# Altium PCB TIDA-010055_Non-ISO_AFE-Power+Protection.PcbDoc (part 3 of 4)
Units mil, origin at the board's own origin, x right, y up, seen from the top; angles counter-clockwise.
Board outline 3622.05 x 4330.71 mil, 4 copper layers (Top Layer, GND Layer, PWR Layer, Bottom Layer), stack 63.6 mil thick; 398 components, 177 nets, 1104 pads, 428 vias.
Unrouted connection lines stored in the file: 1.
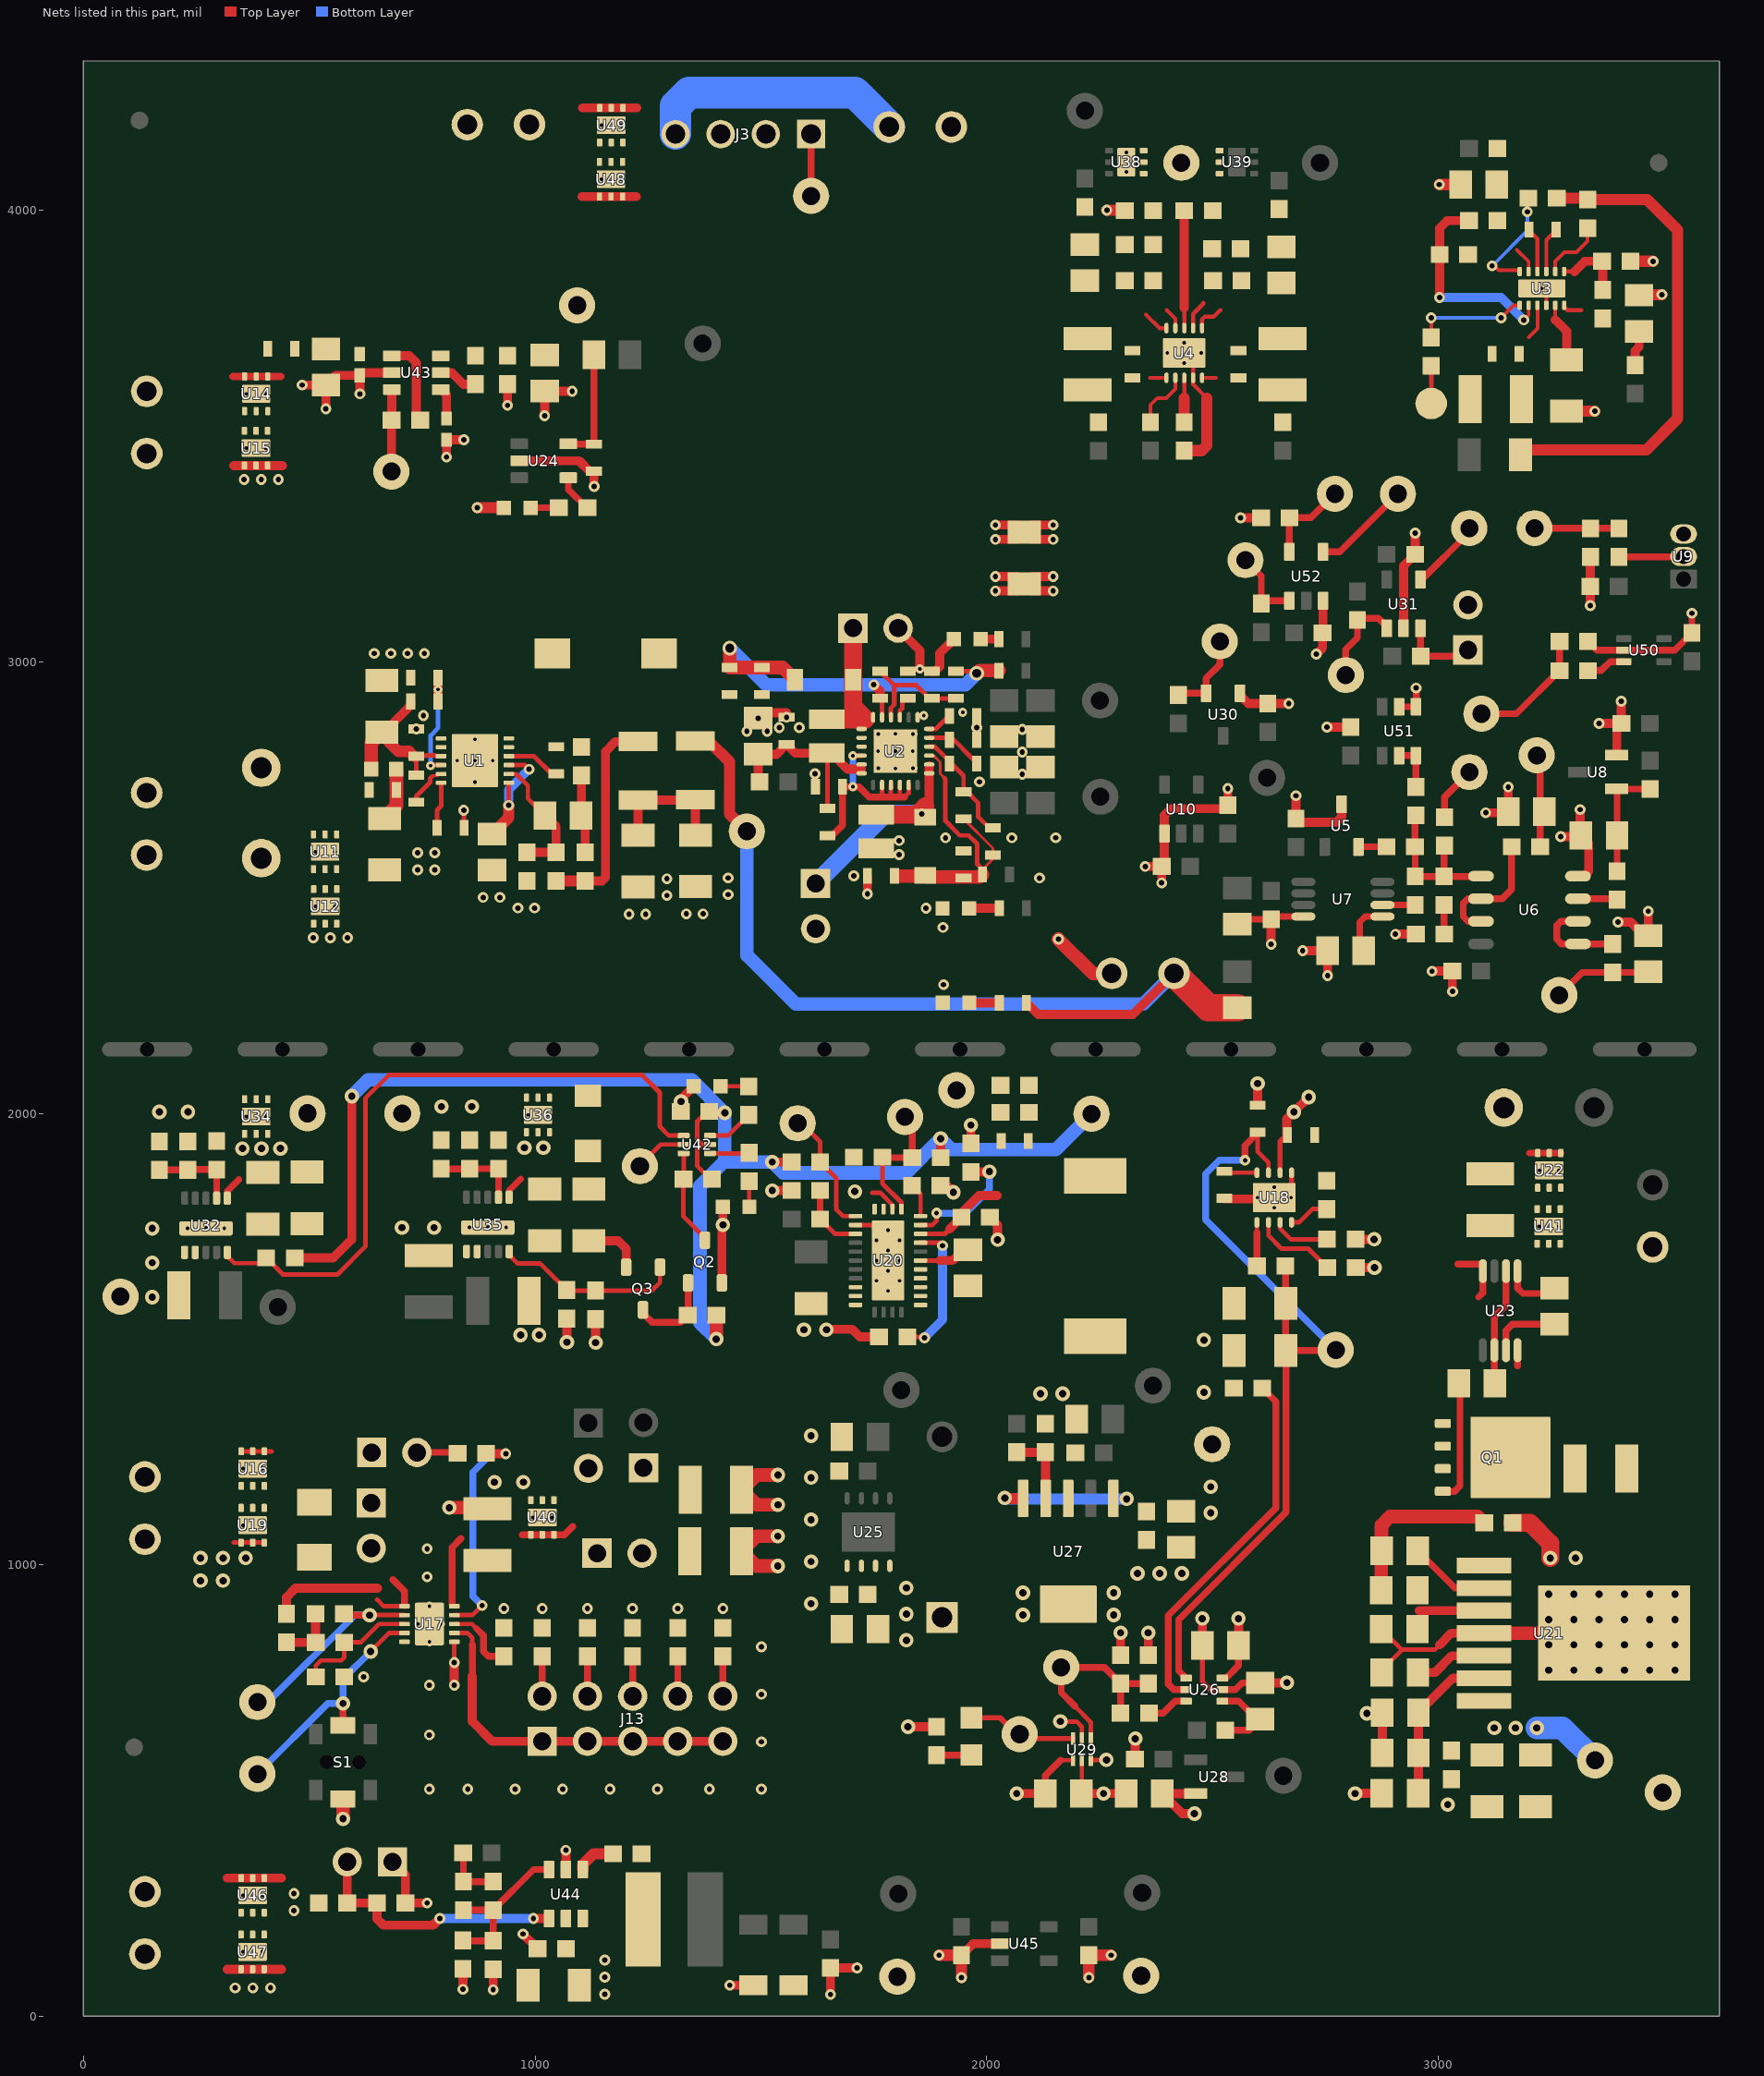
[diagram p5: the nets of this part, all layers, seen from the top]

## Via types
v1: diameter 24, hole 12, Top Layer to Bottom Layer, tented both sides, 201 vias
v2: diameter 32, hole 16, Top Layer to Bottom Layer, tented both sides, 134 vias
v3: diameter 19.68, hole 7.87, Top Layer to Bottom Layer, 78 vias
v4: diameter 20, hole 8, Top Layer to Bottom Layer, tented both sides, 11 vias
v5: diameter 32, hole 20, Top Layer to Bottom Layer, tented both sides, 2 vias
v6: diameter 24, hole 10, Top Layer to Bottom Layer, tented both sides, 2 vias

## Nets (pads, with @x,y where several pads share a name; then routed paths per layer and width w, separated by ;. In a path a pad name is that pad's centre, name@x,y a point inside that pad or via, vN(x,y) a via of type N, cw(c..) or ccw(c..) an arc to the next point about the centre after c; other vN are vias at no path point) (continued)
AGND: C9.1 C32.1 C33.2 C34.2 C35.2 C37.2 C39.2 C41.2 C42.2 C43.1 C44.2 C45.2 C46.2 C47.1 C48.2 C49.1 C50.2 C51.2 C52.2 C53.2 C54.2 C55.2 C56.1 C57.1 C58.2 C59.2 C99.2 C100.2 C135.1 C136.1 C137.2 C138.1 C139.2 J3.3 J15.2 J20.1 J21.1 R32.1 R35.1 R37.1 R51.1 TP32.1 U3.4 U3.13@3229.36,3826.82 U4.4 U4.11 U5.3 U6.4 U7.4 U8.2 U9.3 U10.1 U30.1 U31.2 U38.1 U38.2 U38.3 U38.7@2309,4106.65 U39.4 U39.5 U39.6 U49.4 U49.5 U49.6 U50.2 U51.1 U51.2 U52.3 | length 3644.7
  Top Layer w8: v3(3229.36,3826.82) U3.13@3239.2,3816.98
  Top Layer w9: U4.11@2437.4,3684 2457.09,3664.32 U4.4@2457.09,3628.88 2457.09,3614.32 2487.4,3584 ; U3.4@3239.2,3789.42 U3.13@3239.2,3816.98
  Top Layer w15: C53.2@2554.81,2419.23 2565.31,2429.74 C54.2@2629.81,2429.74 ; C54.2@2635.92,2435.85 U7.4@2701.21,2435.85 ; U51.2@2913,2900.44 U51.1@2950.4,2900.44 2951,2901.04 v1(2951,2942) ; C136.1@3331.25,3045.39 3350.64,3026 U50.2@3410.93,3026 3523.54,3026 C135.1@3561.61,3064.08 v1(3561.61,3107.61)
  Top Layer w20: 1104.61,4226.71 U49.6@1142.98,4226.71 U49.5@1168.57,4226.71 U49.4@1194.16,4226.71 1224.84,4226.71 ; v1(2019.16,3271.1) 2067.24,3271.1 R51.1@2083.16,3287.01 ; v1(2019.16,3302.92) 2067.24,3302.92 R51.1@2083.16,3287.01 ; v1(2147.16,3271.1) 2099.07,3271.1 R51.1@2083.16,3287.01 ; v1(2147.16,3302.92) 2099.07,3302.92 R51.1@2083.16,3287.01 ; v1(2351,2546.72) C58.2@2387.38,2546.7 ; v1(2387.38,2510.35) C58.2@2387.38,2546.7 ; C58.2@2393.47,2552.8 U10.1@2393.47,2619.57 2393.47,2660.2 2408,2674.72 2525.9,2674.72 C59.2@2533.87,2682.7 v1(2533.9,2719.08) ; U30.1@2560.65,2926.31 2579.46,2907.5 C99.2@2622.25,2907.5 v1(2669.04,2907.5) ; v1(2562,3319) C138.1@2607.5,3319 ; v1(2629.81,2374.42) C54.2@2629.81,2429.74 ; v1(2684.81,2703.53) C46.2@2684.81,2652.73 2692.81,2644.72 2774,2644.72 2785.81,2656.53 U5.3@2785.81,2684.48 ; v1(2699.49,2360.23) C48.2@2754.81,2360.23 v1(2754.81,2304.92) ; v1(2729.85,3017) 2743.56,3030.71 C139.2@2743.56,3064.02 2744.76,3065.22 U52.3@2744.76,3135.32 ; v1(2753.5,2855.5) C137.2@2806,2855.5 ; v1@2905.51,2397.23 C55.2@2950.31,2397.23 ; U31.2@2923,3078 2923.06,3078.07 2923.06,3212.77 C100.2@2948.5,3238.2 v1(2948.5,3285.13) ; v1@2986.51,2315.23 C47.1@3031.31,2315.23 v1@3031.31,2270.43 ; v1(3105,2665.72) 3152.3,2665.72 C52.2@3154.81,2668.23 3155,2668.43 v1(3155,2722.72) ; v1(3271,2612.72) 3313.3,2612.72 C51.2@3315.3,2614.73 ; U6.4@3309.09,2525.23 3322.51,2525.23 3333,2535.72 3333,2598.04 C51.2@3315.81,2615.23 3314,2617.04 v1(3314,2672.72) ; v1(3336.5,3124.5) C56.1@3336.5,3167 3336.5,3232.01 C57.1@3337,3232.5 ; v1(3355.69,2863.72) C49.1@3404.35,2863.72 ; U8.2@3395.19,2793.13 3395.19,2853.56 C49.1@3405.35,2863.72 ; v1(3398,2423.72) 3426,2423.72 3456,2393.72 C50.2@3464.85,2393.72 v1(3464.85,2447.57) ; C49.1@3404.85,2864.23 v1(3404.85,2912.88)
  Top Layer w25: v1(2266,4000) 2304.91,4000 R35.1@2305.91,3999 ; C42.2@2437.4,3467.5 2475.91,3467.5 2487.4,3479 2487.4,3584 ; v1(3002.19,4056.98) C34.2@3049.2,4056.98 ; C45.2@3284.2,3554.9 v1(3346.36,3554.9) ; R37.1@3425.7,3886.98 v1(3475.7,3886.98) ; C39.2@3444.2,3811.98 3445.44,3813.23 v1(3494.83,3813.23)
  other v1: 3031.82,2269.92 2986,2314.72 2905,2396.72
  other v3: 2437.4,3661.36 2400,3684 2474.8,3684 2437.4,3706.64 2309,4085 2309,4128.31
DCDC_+10P5V: C102.1 C103.1 R88.2 TP20.1 U32.6 U34.4 U34.5 U34.6 | length 51.5
  Top Layer w15: U32.6@318.35,1812.08 318.35,1827.35 344,1853
  other v2: 352,1922 394,1922 436,1922
DCDC_-10P5V: C105.2 C106.2 C107.2 D4.2 Q3.2 R92.1 R93.1 TP22.1 U35.1 U35.2 U35.11@895.2,1747.09 U36.1 U36.2 U36.3 U36.7@1006.37,1996.6 | length 130.6
  Top Layer w20: C107.2@1119.09,1717.78 1183.7,1717.78 1201.6,1699.88 Q3.2@1201.6,1659.24
  other v2: 705.09,1746.86 776.09,1746.94 792.75,2014.94 859.75,2014.94
  other v3: 854.65,1747.09 895.2,1747.09 935.75,1747.09 984.72,1996.6 1028.03,1996.6
EXT_5V: C61.1 C84.1 C121.1 R104.2 R113.1 TP43.1 U24.5 U43.6 | length 255.2
  Top Layer w15: U24.5@1073.32,3482.6 1073.72,3482.2 C84.1@1130.18,3482.2 1130.18,3680.05 R113.1@1129.99,3680.25
GND: C3.2 C4.2 C5.2 C8.2 C10.2 C16.2 C17.2 C18.2 C19.2 C21.2 C22.2 C23.2 C25.1 C26.1 C27.1 C28.1 C29.2 C30.2 C31.2 C60.2 C61.2 C84.2 C120.2 C121.2 C122.2 D1.2 D6.2 D10.1 D11.2 J1.2 J4.2 J6.1 J8.2 J12.2 L5.2 R8.1 R9.1 R10.1 R11.1 R16.1 R51.2 U1.1 U1.2 U1.13 U2.2 U2.3 U2.19 U2.25 U12.4 U12.5 U12.6 U15.4 U15.5 U15.6 U24.2 U43.2 | length 1700.5
  Top Layer w10: v1(841.88,2671.43) 841.88,2633.01 C10.2@842.73,2632.16
  Top Layer w20: 332.76,3434.69 U15.4@356.4,3434.69 U15.5@381.99,3434.69 U15.6@407.58,3434.69 440.76,3434.69 ; v1(484.08,3612.97) C60.2@536.66,3612.97 ; v1(536.66,3560.4) C60.2@536.66,3612.97 ; v1(611.81,3593.25) C120.2@611.81,3634.63 ; U43.2@682.67,3640.25 617.43,3640.25 C120.2@611.81,3634.63 ; v1(803.81,3453.25) C122.2@803.81,3491.63 v1(842.19,3491.63) ; v1(938.99,3568.01) C61.2@938.99,3614.75 ; U24.2@965.05,3445.2 1097.5,3445.2 1120.5,3422.2 C84.2@1130.18,3422.2 v1@1130.18,3388.61 ; v1(1020.99,3545) C121.2@1020.99,3599.25 v1(1082.25,3599.25) ; v1(1493.73,2875.16) 1505.73,2887.16 v1@1556.73,2887.16 ; C28.1@1735.73,2526.16 1736,2525.89 v1(1736,2486) ; J8.2@1804.73,3072.16 1851.73,3025.16 v4(1851.73,2984.16) ; R16.1@1878.73,2979.16 1885.41,2979.16 1895.88,2989.63 1895.88,3018.83 D6.2@1927.2,3050.16 ; D10.1@1902.2,2454.16 D10.1@1902.32,2454.04 ; v1(2019.16,3156.92) 2067.24,3156.92 R51.2@2083.16,3172.84 ; v1(2019.16,3188.75) 2067.24,3188.75 R51.2@2083.16,3172.84 ; v1(2147.16,3156.92) 2099.07,3156.92 R51.2@2083.16,3172.84 ; v1(2147.16,3188.75) 2099.07,3188.75 R51.2@2083.16,3172.84 ; C60.2@536.66,3612.97 558.31,3634.63 C120.2@611.81,3634.63
  Top Layer w25: v1(872.02,3341.2) D11.2@931.07,3341.2
  Top Layer w30: v1(2158.85,2385.72) 2234.85,2309.72 J6.1@2276.85,2309.72
  other v1: 1904.43,2285 508.66,2388.76 546.66,2388.76 584.66,2388.76 1903,2411.68 1207.88,2441.04 1244.88,2441.04 1334.88,2441.76 1371.88,2441.76 961.88,2454.67 998.88,2454.67 1865.53,2454.16 884.88,2478.17 921.88,2478.17 1291.88,2482.43 1427.61,2484.43 1291.88,2519.43 1427.61,2521.43 2116.73,2521.16 1705.73,2526.16 739.88,2539.16 777.88,2539.16 1806,2573 739.88,2577.16 777.88,2577.16 1806,2604 1908.73,2610.16 2055.73,2610.16 2152.88,2610.43 1983.73,2734.16 2078.73,2751.16 1619.73,2752.16 2078.73,2800.16 1468.73,2846.16 1513.73,2846.16 2078.73,2850.16 736.73,2851.16 1540.73,2854.16 1584.73,2854.16 1977.73,2854.16 1556.73,2877.16 752.73,2881.16 643.73,3018.51 680.73,3018.51 717.73,3018.51 754.73,3018.51 1130.6,3388.2 355.48,3403.68 393.48,3403.68 431.48,3403.68
  other v3: 866.73,2733.91 1797.73,2763.77 827.36,2781.16 866.73,2781.16 906.1,2781.16 1759.35,2802.16 1797.73,2802.16 1836.12,2802.16 866.73,2828.4 1797.73,2840.54
  other v4: 1759.73,2764.16 1836.73,2764.16 1759.81,2840.08 1836.73,2840.16 1860.73,2881.16 1946.73,2888.16
GND1: C63.2 C64.2 C65.2 C66.2 C68.2 C69.2 C70.1 C71.2 C72.2 C74.2 C76.2 C77.2 C78.2 C79.2 C80.2 C81.2 C82.2 C83.1 C85.1 C86.1 C87.1 C88.1 C89.1 C90.1 C91.2 C92.1 C93.1 C94.1 C95.1 C96.1 C97.1 C98.2 C101.2 C102.2 C103.2 C104.2 C106.1 C107.1 C119.2 C133.2 C134.2 D4.1 D14.2 D15.2 J11.2 J14.1 Q2.2 R6.2 R57.1 R69.1 R70.1 R72.2 R73.1 R74.1 R81.1 R84.1 R89.1 R90.1 R91.2 R98.1 R110.1 R111.1 S1.1 TP21.1 TP26.1 TP39.1 TP41.1 U17.6 U18.5 U18.9 U19.4 U19.5 U19.6 U20.13 U20.14 U20.15 U20.17 U20.24 U20.25 U20.26 U20.31@1781.43,1673.99 U21.4 U21.8 U25.1 U26.2 U27.3 U27.6 U28.2 U29.1 U29.3 U29.5 U32.1 U32.2 U32.11@271.11,1745.15 U34.1 U34.2 U34.3 U34.7@382.28,1993 U35.6 U36.4 U36.5 U36.6 U40.1 U40.2 U40.3 U40.7@1016,1105 U41.4 U41.5 U41.6 U42.2 | length 3710.1
  Top Layer w10: 332.25,1049.43 U19.4@348.96,1049.43 U19.5@374.55,1049.43 U19.6@400.14,1049.43 ; v1(820.96,783.41) U17.6@820.96,829.59 ; TP21.1@1230,1883 1278,1931 U42.2@1328.87,1931 ; U20.17@1709.58,1752.73 1743.95,1752.73 1781.43,1715.24 v3(1781.43,1696.43) U20.31@1781.43,1673.99 ; 1747,1824 1764.28,1824 1791.28,1797 U20.13@1791.28,1788.16 ; v2(2163,653) 2199,653 2210.68,641.32 U29.5@2210.68,615.26 ; 2163.23,567.23 U29.1@2191,567.23 ; U29.3@2230.37,568.02 v2(2265,568) ; R69.1@2873.86,857.68 2919.65,811.89 ; C77.2@2874.86,767.1 2919.65,811.89 ; 3003.12,822.89 2992.12,811.89 2919.65,811.89
  Top Layer w12: C89.1@2477.68,821.64 2477.68,740.32 2494.36,723.64 U26.2@2522.04,723.64 ; U18.9@2636.73,1813.43 v3(2674.13,1813.43) ; U18.9@2675.12,1813.43 U18.5@2675.12,1868.54
  Top Layer w15: U35.6@942.44,1814.02 942.44,1829.3 968.09,1854.94 ; v2@1413.94,1752 v2@1415.47,1753.53 ; C97.1@2129.68,493.64 2129.68,533.68 2163.23,567.23 ; U26.2@2522.04,723.64 2550.68,723.64 2565.68,738.64 C96.1@2605.68,738.64
  Top Layer w20: v1(820.96,733.41) v1(820.96,783.41) ; v2(1070.28,1493) R98.1@1070.28,1545.23 ; v2(1134,1492) R6.2@1134,1544.23 ; C119.2@1330.38,2001 1323,2008.38 v2(1323,2026) 1323,2031.53 D14.2@1351.47,2060 ; Q2.2@1413.5,1624.34 1413.5,1751.56 v2@1413.94,1752 ; v2@1415.47,1753.53 D15.2@1415.47,1793 ; v2(1525.21,1828.99) R73.1@1567.94,1828.99 ; v2(1645.12,1520.89) 1646.23,1522 1702,1522 1719,1505 C70.1@1761.5,1505 ; C82.2@1897.5,1840 1911,1840 v2(1926,1825) ; v2(1965,1974) 1965,1933.5 R72.2@1965.12,1933.39 ; C83.1@2007.12,1769.89 2024.12,1752.89 v2(2024.12,1719.89) ; v2(2066.36,493.64) C97.1@2129.68,493.64 ; C91.2@2296.68,800.14 v2(2296.68,849.68) ; R81.1@2357.68,800.14 v2(2357.68,849.68) ; C90.1@2388.68,493.64 C90.1@2389.08,493.24 ; v2(2460,449) 2433.32,449 C90.1@2389.08,493.24 ; U28.2@2460.38,493.24 C90.1@2389.08,493.24 ; C89.1@2477.68,821.64 v2@2477.68,879.6 ; C98.2@2525.99,1810.27 2633.57,1810.27 U18.9@2636.73,1813.43 ; C63.2@2600,2019.5 v2(2600,2066) ; C96.1@2605.68,738.64 v2@2663.64,738.64 ; R111.1@2816.5,1721 v2(2858,1721) ; v2@2817.04,494 R70.1@2875,494 ; R110.1@2817.08,1658.39 v2(2858.58,1658.39) ; 3003.12,822.89 3028.9,848.68 U21.4@3101.26,848.68
  Top Layer w30: v2(574.59,437.63) 574.59,438.63 S1.1@574.59,481.26 ; v2(809.84,1126.66) 890.38,1126.66 C66.2@893.84,1123.19 ; v2(1537.46,997.36) 1489.93,997.36 C69.2@1456.93,1030.36 1489.93,1063.36 v2(1537.46,1063.36) ; v2(1537.74,1132.89) 1490.2,1132.89 C68.2@1457.2,1165.89 1490.2,1198.89 v2(1537.74,1198.89) ; U21.4@3101.26,848.68 U21.8@3388.86,848.68
  Top Layer w40: C79.2@3164.5,1093 3203,1093 3248,1048 v2(3248,1015)
  other v2: 3021,469 2815.68,493.64 2665,739 3244.12,766.89 3300.12,766.89 3356.12,766.89 3412.12,766.89 3468.12,766.89 3524.12,766.89 3244.12,822.89 3300.12,822.89 3356.12,822.89 3412.12,822.89 3468.12,822.89 3524.12,822.89 3244.12,878.89 3300.12,878.89 3356.12,878.89 3412.12,878.89 3468.12,878.89 3524.12,878.89 2477.32,880.96 2080.07,889 2281,889 1611,914 3244.12,934.89 3300.12,934.89 3356.12,934.89 3412.12,934.89 3468.12,934.89 3524.12,934.89 2080.07,938 2281,938 259,965 309,965 2334,981 2383,981 2432,981 1611,1007 259,1015 309,1015 359,1015 3304,1015 1611,1100 910,1183 974,1183 1611,1193 1611,1286 2119,1379 2168,1379 967.75,1508.89 1008.71,1508.89 1595.12,1520.89 152,1593 152,1669 152,1745 1416,1753 1708,1827 976.09,1923.94 1018.09,1923.94 168,2003 231.11,2003
  other v3: 994.35,1105 1037.65,1105 1781.43,1606.66 1755.84,1629.1 1807.02,1629.1 1781.43,1651.54 1755.84,1673.99 1807.02,1673.99 1755.84,1718.87 1807.02,1718.87 1781.43,1741.31 230.56,1745.15 271.11,1745.15 311.66,1745.15 2636.73,1790.79 2599.33,1813.43 2636.73,1836.06 360.63,1993 403.94,1993
GND_S: C123.2 C124.2 C125.2 C126.2 C129.2 C130.2 C131.1 C132.2 J18.1 J19.2 R107.1 R109.1 TP35.1 TP37.1 U44.2 U45.2 U47.4 U47.5 U47.6 | length 914.5
  Top Layer w20: 318.14,104.43 U47.4@348.82,104.43 U47.5@374.41,104.43 U47.6@400,104.43 438.37,104.43 ; J18.1@684,342 712.99,313.01 R107.1@712.99,251 v1(761,251) ; v1(840.07,59.98) C132.2@840.07,105.48 ; v1(907.07,58.98) R109.1@907.07,104.48 ; v1(973.07,182.48) C124.2@1005.57,149.98 ; U44.2@1068.07,325.11 v1(1068.07,367.98) ; v1(1431.07,68.98) 1483,68.98 C129.2@1483.07,69.05 ; v1(1654.07,48.55) C131.1@1654.07,107.48 v1(1713,107.48) ; C125.2@1944.07,135.48 1969.5,160.91 2028.94,160.91 U45.2@2028.94,160.98
  Top Layer w25: v1(1894.57,135.48) C125.2@1944.07,135.48 v1(1944.07,85.98) ; v1(2226.07,85.98) C126.2@2226.07,135.48 v1(2275.57,135.48)
  other v1: 336,63 375,63 414,63
NetC1_1: C1.1 C6.1 C7.1 J6.2 L2.2 R1.1 R7.2 R112.1 TP24.1 | length 2577.3
  Top Layer w20: C1.1@1110.88,2514.94 1148.39,2514.94 1155.92,2522.47 1155.92,2801.56 1177.71,2823.35 C6.1@1227.88,2823.35 ; R1.1@2087.85,2244.72 2113.85,2218.72 2323.65,2218.72 J6.2@2414.65,2309.72
  Top Layer w25: R7.2@1046.32,2514.94 C1.1@1110.88,2514.94 ; C7.1@1354.88,2824.35 1384.65,2824.35 1430.42,2778.59 1430.42,2662.9 TP24.1@1468.88,2624.43
  Top Layer w60: J6.2@2414.65,2309.72 2490.37,2234 R112.1@2555,2234
  Bottom Layer w30: TP24.1@1468.88,2624.43 1468.88,2350.12 1577,2242 2346.92,2242 J6.2@2414.65,2309.72
NetC1_2: C1.2 C11.1 R5.2 | length 174.5
  Top Layer w20: R5.2@1102.47,2748.45 1102.47,2660.02 C11.1@1101.88,2659.43 1110.88,2650.43 C1.2@1110.88,2577.93
NetC2_1: C2.1 U1.10 | length 121.2
  Top Layer w10: U1.10@941.54,2791 997.48,2791 1036.54,2751.94 C2.1@1046.54,2751.94
NetC2_2: C2.2 L2.1 R5.1 U1.11 U1.12
NetC3_1: C3.1 L1.1 R2.1 | length 117.2
  Top Layer w30: C3.1@666.73,2653.24 666.73,2655.16 692.73,2681.16 R2.1@692.73,2716.16 L1.1@692.73,2759.72
NetC4_1: C4.1 C5.1 L1.2 R3.1 R4.2 U1.3 | length 402.3
  Top Layer w10: R3.1@736.73,2749.16 736.73,2787.51 741.26,2792.03 758.26,2792.03 759.12,2792.89 778.35,2792.89 780.24,2791 U1.3@791.93,2791
  Top Layer w20: C4.1@637.17,2820.51 C4.1@637.17,2845.87 ; C4.1@660.73,2844.07 665.4,2844.07 724.73,2903.41 R4.2@724.73,2912.16
  Top Layer w25: C4.1@659.73,2838.76 696.73,2801.76 720.81,2801.76 C5.1@731.41,2791.16
  Top Layer w30: L1.2@637.17,2762.16 637.17,2820.51 C4.1@660.73,2844.07
NetC6_2: C6.2 C7.2 R8.2 R9.2 | length 283.6
  Top Layer w20: R9.2@1227.88,2615.48 C6.2@1227.88,2693.43 1353.88,2693.43 C7.2@1354.88,2694.43 R8.2@1354.88,2616.2
NetC8_1: C8.1 U1.7 U1.9 | length 276.3
  Top Layer w10: v1(941.54,2682.13) U1.7@941.54,2731.94 ; U1.9@941.54,2771.31 977.37,2771.31 v1(986.74,2761.94)
  Top Layer w25: C8.1@904.88,2618.43 941.54,2655.09 v1(941.54,2682.13)
  Bottom Layer w20: v1(941.54,2682.13) 941.54,2716.74 v1(986.74,2761.94)
NetC9_2: C9.2 C33.1 R19.1 R31.1 R36.1 U3.3 | length 1173.8
  Top Layer w8: 3200.2,3718.98 3219.52,3738.3 U3.3@3219.52,3789.42
  Top Layer w20: R36.1@3327.19,4026.98 R36.1@3330.7,4023.48
  Top Layer w25: R19.1@3182.36,3458.82 3192.76,3469.23 3460.7,3469.23 3529.98,3538.5 3529.98,3956.08 3462.58,4023.48 R36.1@3330.7,4023.48 ; R31.1@3262.19,4026.98 R36.1@3327.19,4026.98
NetC10_1: C10.1 U1.6 | length 103.6
  Top Layer w10: C10.1@782.73,2632.16 782.73,2671.28 791.93,2680.48 U1.6@791.93,2731.94
NetC11_2: C11.2 R7.1 R11.2 U1.8 | length 291.1
  Top Layer w10: U1.8@941.54,2751.63 957.88,2751.63 983.88,2725.63 983.88,2697.43 C11.2@1021.88,2659.43
  Top Layer w20: R11.2@981.88,2577.93 R7.1@1046.32,2577.93 1046.32,2635 C11.2@1021.88,2659.43
NetC18_1: C18.1 C19.1 C20.1 D7.1 R15.2 R22.1 U2.23 | length 967
  Top Layer w10: U2.23@1768.2,2876.96 C20.1@1768.2,2918.63 ; R15.2@1931.73,2979.16 1973.16,2979.16 v5(1977.88,2974.43)
  Top Layer w20: v1(1750.05,2949.16) 1763.73,2935.48 C20.1@1763.73,2919.16
  Top Layer w30: v5(1430.88,3030.43) 1430.73,3030.28 C18.1@1430.73,2987.43 C19.1@1501.88,2987.43 1547.99,2987.43 D7.1@1575.26,2960.16 ; v5(1977.88,2974.43) 1983.88,2980.43 R22.1@2026.88,2980.43
  Bottom Layer w30: v5(1430.88,3030.43) 1512.16,2949.16 v1(1750.05,2949.16) 1952.61,2949.16 v5(1977.88,2974.43)
NetC20_2: C20.2 R15.1 R16.2 U2.22 | length 310.5
  Top Layer w10: C20.2@1763.73,2979.16 1794.11,2948.78 1794.11,2903.82 ; U2.22@1787.89,2876.96 1787.89,2897.16 ; 1787.89,2897.61 1794.11,2903.82 ; R15.1@1931.73,2919.16 R16.2@1878.73,2919.16 1872.73,2919.16 1843.46,2948.43 1795.36,2948.43 1795.36,2905.08 1794.11,2903.82
NetC21_1: C21.1 R17.2 U2.17 | length 120
  Top Layer w10: U2.17@1872.54,2831.69 1911.2,2831.69 C21.1@1915.73,2827.16 ; C21.1@1919.73,2834.48 R17.2@1972.73,2781.48
NetC22_1: C22.1 C23.1 L3.2 L4.1 R20.2 U2.5 U2.6 | length 443.9
  Top Layer w10: R20.2@1647.73,2675.16 L4.1@1647.73,2795.76
  Top Layer w20: L3.2@1497.24,2734.16 1493.73,2737.66 C22.1@1493.73,2795.16 1534.73,2795.16 C23.1@1556.73,2817.16 1576.13,2797.76 L4.1@1645.73,2797.76 1656.13,2797.76 1691.73,2762.16 1722.73,2762.16
NetC24_1: C24.1 R17.1 R18.2 U2.16 | length 258.9
  Top Layer w10: U2.16@1872.54,2812 1884.82,2812 1897.22,2799.6 1897.22,2799.54 1948.73,2748.03 C24.1@1948.73,2712.16 1956.73,2712.16 1980.73,2688.16 1980.73,2657.16 R18.2@2005.73,2632.16 ; R18.2@2001.73,2632.16 R18.2@2005.73,2632.16 ; R18.2@2013.73,2632.16 R18.2@2005.73,2632.16
NetC24_2: C24.2 C27.2 C28.2 D8.2 R18.1 R23.1 U2.15 | length 672.3
  Top Layer w6: U2.15@1872.54,2792.31 1882,2792.31 1896.73,2777.58 1896.73,2752.16 1905.73,2743.16 ; C24.2@1948.73,2652.16 2013.73,2587.16 R18.1@2013.73,2572.16 2013.73,2563.16 1990.73,2540.16 R23.1@1990.73,2529.16
  Top Layer w10: 1905.73,2743.16 1908.61,2740.28 1908.61,2647.71 1940.88,2615.43 1960.16,2615.43 1979.11,2596.49 1979.11,2551.78 R23.1@1990.73,2540.16
  Top Layer w30: C28.2@1800.73,2525.16 1862.07,2525.16 D8.2@1863.88,2526.96 1867.74,2523.11 1984.68,2523.11 R23.1@1990.73,2529.16
NetC29_1: C29.1 R20.1 U2.4 U2.8 U2.9 U2.10 U2.11 | length 474.8
  Top Layer w10: v4(1703.73,2792.16) 1703.89,2792.31 U2.4@1722.93,2792.31 ; 1768.2,2700.64 U2.8@1768.2,2727.35 ; 1787.89,2700.33 U2.9@1787.89,2727.35 ; 1807.57,2700.33 U2.10@1807.57,2727.35 ; 1818.23,2700.17 1827.26,2709.2 U2.11@1827.26,2727.35
  Top Layer w15: R20.1@1647.73,2615.16 1658.23,2615.16 1680.73,2637.66 C29.1@1680.73,2723.16 v4(1703.73,2723.16) 1717.21,2723.16 1740.19,2700.17 1818.23,2700.17
  Bottom Layer w15: v4(1703.73,2723.16) v4(1703.73,2792.16)
NetC30_1: C30.1 U2.18 | length 55.1
  Top Layer w10: U2.18@1872.54,2851.37 1886.94,2851.37 C30.1@1915.73,2880.16
NetC31_1: C31.1 U2.21 | length 48.1
  Top Layer w10: U2.21@1807.57,2876.96 1807.57,2892.02 1813.23,2897.67 1813.23,2910.66 C31.1@1821.73,2919.16
NetC32_2: C32.2 C35.1 R26.2 U4.1 | length 36.6
  Top Layer w8: 2361.4,3628.88 U4.1@2398.03,3628.88
NetC34_1: C34.1 R24.1 R27.2 U3.11 | length 58.4
  Top Layer w8: 3174.2,3911.98 3199.83,3886.35 U3.11@3199.83,3864.23
NetC36_1: C36.1 C37.1 R25.1 R28.2 U4.10 | length 58
  Top Layer w9: 2352.4,3769 2382.28,3739.12 U4.10@2398.03,3739.12
NetC36_2: C36.2 R28.1 R35.2 U4.9 | length 47.9
  Top Layer w9: 2398.4,3779 2417.72,3759.69 U4.9@2417.72,3739.12
NetC38_1: C38.1 U3.9 | length 102.3
  Top Layer w9: U3.9@3239.2,3864.23 3239.2,3933.99 C38.1@3262.19,3956.98
NetC38_2: C38.2 U3.10 | length 101.2
  Top Layer w9: C38.2@3199.2,3956.98 3219.52,3936.67 U3.10@3219.52,3864.23
NetC39_1: C39.1 R30.2 R40.1 U3.6 | length 128.5
  Top Layer w9: U3.6@3278.57,3789.42 3278.57,3786.11 3285.7,3778.98 3316.7,3778.98
  Top Layer w20: R30.2@3360.26,3764.42 R30.2@3364.2,3760.49 ; R40.1@3435.7,3656.98 3435.7,3688.48 3444.2,3696.98 C39.1@3444.2,3731.98
NetC40_1: C40.1 C41.1 R34.2 R41.1 U4.6 | length 68.4
  Top Layer w9: U4.6@2476.77,3739.12 2476.77,3758.37 2482.4,3764 2502.4,3764 2517.4,3779
NetC40_2: C40.2 R34.1 R39.2 U4.7 | length 65.1
  Top Layer w9: U4.7@2457.09,3739.12 2457.09,3770.69 2479.4,3793 2479.4,3795
NetC42_1: C42.1 U4.3 | length 98.4
  Top Layer w9: 2437.4,3584 U4.3@2437.4,3628.88
  Top Layer w25: C42.1@2437.4,3530.5 2437.4,3584
NetC43_2: C43.2 C44.1 R33.2 U4.5 | length 30.5
  Top Layer w9: U4.5@2476.77,3628.88 2507.28,3628.88
NetC45_1: C45.1 U3.5 | length 130.8
  Top Layer w8: 3258.89,3757.3 U3.5@3258.89,3789.42
  Top Layer w20: 3258.89,3757.3 3284.2,3731.98 C45.1@3284.2,3669.07
NetC48_1: C48.1 U7.5 | length 122.6
  Top Layer w15: C48.1@2834.81,2360.23 2826,2369.04 2826,2423.72 2838.12,2435.85 U7.5@2876.41,2435.85
NetC51_1: C51.1 R46.2 R47.1 U8.1 | length 256
  Top Layer w15: R47.1@3395.81,2536.23 C51.1@3395.81,2615.23 3395.81,2717.7 U8.1@3395.19,2718.32 3468.76,2718.32 R46.2@3468.85,2718.23
NetC55_1: C55.1 R49.2 | length 64.7
  Top Layer w15: R49.2@3012.81,2461.74 3012.81,2397.73 C55.1@3013.3,2397.23
NetC60_1: C60.1 C120.1 R52.1 R103.2 U43.1 | length 191
  Top Layer w20: U43.1@682.67,3677.65 721.41,3677.65 736.81,3662.25 736.81,3543.75 R103.2@745.3,3535.25
NetC67_1: C67.1 U17.8 | length 160
  Top Layer w10: U17.8@820.96,868.96 860.17,868.96 870.84,858.29
  Top Layer w15: 870.84,858.29 885.84,843.29 885.84,808.29 896.67,797.46 C67.1@930.84,797.46
NetC67_2: C67.2 R58.1 R59.1 R60.1 R61.1 R62.1 R63.1 U17.5 U17.11@765.84,868.96
  other v1: 765.84,503.29 850.84,503.29 955.84,503.29 1060.84,503.29 1165.84,503.29 1270.84,503.29 1385.84,503.29 1500.84,503.29 1500.84,608.29 765.84,623.29 1500.84,713.29 765.84,733.29 620.17,752.11 1500.84,818.29 930.84,903.29 1015.84,903.29 1115.84,903.29 1215.84,903.29 1315.84,903.29 1415.84,903.29 760.84,973.29 760.84,1035.66
  other v3: 765.84,829.59 741.24,868.96 790.45,868.96 765.84,908.33
NetC68_1: C68.1 C69.1 J10.2
NetC70_2: C70.2 U20.8 | length 310.4
  Top Layer w10: C70.2@1824.5,1505 1860,1505 v1(1862,1503) ; U20.8@1853.28,1713.36 1895.65,1713.36 v1(1902.12,1706.89)
  Bottom Layer w20: v1(1862,1503) 1902.12,1543.12 v1(1902.12,1706.89)
NetC73_2: C73.2 R66.1 R70.2 U21.6 | length 355.9
  Top Layer w20: R70.2@2955,494 2955.86,494.86 C73.2@2955.86,583.68 R66.1@2955.86,672.68 ; R66.1@2955.86,672.68 3031.9,748.68 U21.6@3101.26,748.68
NetC75_1: C75.1 U20.6 | length 114.7
  Top Layer w10: U20.6@1853.28,1673.99 1897.12,1673.99
  Top Layer w20: 1897.12,1673.99 1924.21,1673.99 1948.12,1697.89 C75.1@1958.12,1697.89
NetC75_2: C75.2 L7.1 U20.1 U20.2 U20.3 U20.4 U20.5
NetC77_1: C77.1 U21.5 | length 161.7
  Top Layer w20: C77.1@2954.86,761.68 2992.91,761.68 3029.9,798.68 U21.5@3101.26,798.68
NetC78_1: C78.1 PT2.2 Q1.1 Q1.2 Q1.3 U22.4 U22.5 U22.6 U23.4 | length 199.2
  Top Layer w15: 3043,1666 3093,1666 3098.61,1660.39 U23.4@3098.61,1650.6 3098.61,1602.61 3089,1593 ; 3201.3,1912 U22.6@3220,1912 U22.5@3245.59,1912 U22.4@3271.18,1912
NetC79_1: C79.1 C133.1 Q1.5 Q1.6 Q1.7 Q1.8 Q1.9@3159.61,1238 R65.2 R71.2 U21.1 U23.8 | length 424.5
  Top Layer w15: 3175.39,1440.39 U23.8@3175.39,1475.4 U23.8@3175.39,1479.34
  Top Layer w30: R65.2@2873.86,943.68 2873.86,1031.05 R71.2@2874.12,1031.31 2874.12,1088.12 2893,1107 3087.5,1107 C79.1@3101.5,1093
NetC82_1: C82.1 U20.11 | length 75.5
  Top Layer w10: C82.1@1834.5,1840 1853.43,1821.07 1853.43,1772.56 U20.11@1853.28,1772.41
NetC96_2: C96.2 R83.2 U26.1 | length 187.8
  Top Layer w15: U26.1@2522.04,698.05 2557.95,698.05 2597.36,658.64 C96.2@2605.68,658.64 2580.68,633.64 R83.2@2528.18,633.64
NetC122_1: C122.1 U43.4 | length 70.6
  Top Layer w20: U43.4@790.94,3602.85 793.21,3602.85 803.81,3592.25 C122.1@803.81,3538.87
NetC123_1: C123.1 C124.1 J19.1 R105.2 U44.5 U46.4 U46.5 U46.6 | length 120.2
  Top Layer w20: 318.39,306.39 U46.6@349.06,306.39 U46.5@374.65,306.39 U46.4@400.24,306.39 438.61,306.39
  other v1: 1154.07,48.98 1154.07,86.98 1154.07,124.98 466,234 466,272
NetC127_1: C127.1 U44.1 | length 88.1
  Top Layer w25: U44.1@1105.47,325.11 1105.47,336.38 1129.07,359.98 C127.1@1172.57,359.98
NetC127_2: C127.2 L8.1 U44.6
NetC128_1: C128.1 R106.1 R108.2 | length 129.7
  Top Layer w15: R106.1@840.57,361.98 841.07,361.48 C128.1@841.07,298.47 R108.2@907.07,298.47
NetC128_2: C128.2 C132.1 R108.1 R109.2 U44.3 | length 362.1
  Top Layer w15: C132.1@840.07,168.47 841.07,167.47 R109.2@907.07,167.47 R108.1@907.07,235.48 ; C128.2@841.07,235.48 R108.1@907.07,235.48 ; U44.3@1030.67,325.11 996.7,325.11 R108.1@907.07,235.48
NetC138_2: C138.2 TP47.1 U52.5 | length 198.1
  Top Layer w15: U52.5@2669.95,3243.59 2669.95,3318.46 C138.2@2670.5,3319 2718,3319 TP47.1@2771,3372
NetD1_1: D1.1 R1.2 | length 66
  Top Layer w20: D1.1@1961.85,2244.72 R1.2@2027.85,2244.72
NetD6_1: D6.1 R14.2 | length 40.5
  Top Layer w20: D6.1@1986.26,3050.16 R14.2@2026.73,3050.16
NetD7_2: D7.2 J8.1 L4.2 U2.1 U2.24 | length 297.6
  Top Layer w40: L4.2@1645.73,2872.56 1732,2872.56 1704.2,2900.36 D7.2@1704.2,2960.16 1704.2,3071.63 J8.1@1704.73,3072.16
NetD8_1: D8.1 J12.1 L5.1 U2.13 U2.14 | length 508
  Top Layer w20: 1863.73,2679.63 1872.54,2688.43 U2.13@1872.54,2752.94 U2.14@1872.54,2769.72
  Top Layer w40: L5.1@1755.73,2661.56 1845.67,2661.56 1863.73,2679.63
  Bottom Layer w40: J12.1@1621,2509 1775,2663 v1(1856,2663)
NetD10_2: D10.2 R21.1 | length 66.5
  Top Layer w20: D10.2@1961.26,2454.16 R21.1@2027.73,2454.16
NetD11_1: D11.1 R75.2 | length 64.1
  Top Layer w15: D11.1@990.13,3341.2 R75.2@1052.69,3341.2 R75.2@1054.18,3341.2
NetD13_1: D13.1 R85.1 | length 77.1
  Top Layer w15: R85.1@1889,578.5 1889.16,578.66 D13.1@1966,578.66
NetD13_2: D13.2 TP16.1 U29.6 | length 244.1
  Top Layer w12: D13.2@1966,661.34 2029.66,661.34 2075.74,615.26 U29.6@2191,615.26
NetD14_1: D14.1 R99.2 | length 62.7
  Top Layer w10: D14.1@1410.53,2060 1472.5,2060 R99.2@1473,2059.5
NetD15_1: D15.1 R100.2 | length 56.7
  Top Layer w10: R100.2@1474,1849.5 1474,1793.53 D15.1@1474.53,1793
NetJ1_1: J1.1 R52.2 U14.4 U14.5 U14.6 | length 105.1
  Top Layer w17: 331.45,3632 U14.6@356.65,3632 U14.5@382.24,3632 U14.4@407.83,3632 436.52,3632
NetJ3_1: J3.1 TP42.1 | length 137
  Top Layer w15: TP42.1@1610.98,4031.71 J3.1@1610.98,4168.71
NetJ4_1: J4.1 PT1.1
NetJ7_2: J7.2 R53.2 | length 114.2
  Top Layer w15: J7.2@737.84,1232.66 J7.2@754.18,1249 ; J7.2@738,1249 J7.2@754.18,1249 ; R53.2@828.27,1247.09 826.37,1249 J7.2@754.18,1249
NetJ13_1: J13.1 J13.3 J13.5 J13.7 J13.9 U17.7 | length 802.8
  Top Layer w10: U17.7@820.96,849.27 849.86,849.27 860.84,838.29 860.84,823.29
  Top Layer w15: 860.84,753.29 860.84,823.29
  Top Layer w20: 860.84,753.29 860.84,653.29 905.17,608.96 J13.1@1015.84,608.96 J13.3@1115.84,608.96 J13.5@1215.84,608.96 J13.7@1315.84,608.96 J13.9@1415.84,608.96
NetJ13_2: J13.2 R59.2 | length 88.5
  Top Layer w15: J13.2@1015.84,708.96 R59.2@1015.84,797.46
NetJ13_4: J13.4 R60.2 | length 88.5
  Top Layer w15: J13.4@1115.84,708.96 R60.2@1115.84,797.46
NetJ13_6: J13.6 R61.2 | length 88.5
  Top Layer w15: J13.6@1215.84,708.96 R61.2@1215.84,797.46
NetJ13_8: J13.8 R62.2 | length 88.5
  Top Layer w15: J13.8@1315.84,708.96 R62.2@1315.84,797.46
NetJ13_10: J13.10 R63.2 | length 88.5
  Top Layer w15: J13.10@1415.84,708.96 R63.2@1415.84,797.46
NetJ15_1: J15.1 R94.2 U31.3 | length 176.4
  Top Layer w15: U31.3@2960.4,3078 U31.3@2960.4,3074.07 2960.4,3012.81 R94.2@2961.04,3012.18 3051.54,3012.18 J15.1@3065.54,3026.18
NetJ17_2: J17.2 R54.2 U17.1 | length 383.1
  Top Layer w10: 650,923 664.67,908.33 U17.1@710.72,908.33 U17.1@710.72,910.1
  Top Layer w15: 685.03,967.47 710.72,941.78 U17.1@710.72,910.1
  Top Layer w20: R54.2@449.29,891.65 449.29,928.29 469.29,948.29 650.84,948.29
NetJ18_2: J18.2 R105.1 R107.2 U44.4 | length 584.6
  Top Layer w20: J18.2@584,342 R105.1@584,251 R107.2@650,251 650,216 664,202 774.23,202 v1(789.07,216.84) ; v1(996.2,216.84) U44.4@1030.67,216.84
  Bottom Layer w20: v1(789.07,216.84) v1(996.2,216.84)
NetPT1_2: PT1.2 R2.2 U11.4 U11.5 U11.6
NetQ1_4: Q1.4 R95.2 | length 271.2
  Top Layer w15: Q1.4@3010,1163 3036,1163 3048,1175 3048,1399 R95.2@3045,1402
NetQ2_1: Q2.1 Q3.3 R101.1 | length 193.4
  Top Layer w15: Q3.3@1239,1564.76 1239,1557 1259,1537 1322.17,1537 R101.1@1338.09,1552.92 1338.7,1553.54 Q2.1@1338.7,1624.34
NetQ2_3: Q2.3 R102.1 U42.3 | length 212.4
  Top Layer w10: U42.3@1328.87,1911.32 1328.87,1854.36 R102.1@1328.5,1854 1328.5,1771.5 1376.1,1723.9 Q2.3@1376.1,1718.82
NetR3_2: R3.2 U1.5 | length 94
  Top Layer w6: 771.73,2746.16 773.73,2748.16 785.02,2748.16 788.49,2751.63 U1.5@791.93,2751.63
  Top Layer w10: R3.2@736.73,2689.16 736.73,2702.16 767.23,2732.66 767.23,2741.66 771.73,2746.16
NetR4_1: R4.1 R10.2 U1.4 | length 252
  Top Layer w10: v4(768.73,2770.02) 775.59,2770.02 776.89,2771.31 U1.4@791.93,2771.31
  Top Layer w20: R4.1@784.73,2912.16 v4(784.73,2938.66) R10.2@784.73,2965.16
  Bottom Layer w10: v4(768.73,2770.02) 768.73,2836.7 784.73,2852.7 v4(784.73,2938.66)
NetR27_1: R27.1 R32.2 U3.2 | length 469.4
  Top Layer w8: v1(3189.2,3756.98) 3199.83,3767.61 U3.2@3199.83,3789.42
  Top Layer w20: v1(3002.7,3806.98) R32.2@3002.7,3901.98 3002.7,3960.49 3019.2,3976.98 R27.1@3067.7,3976.98
  Bottom Layer w20: v1(3002.7,3806.98) 3139.2,3806.98 v1(3189.2,3756.98)
NetR29_1: R29.1 TP3.1 | length 83.5
  Top Layer w10: TP3.1@2984.2,3571.98 R29.1@2984.2,3655.49
NetR29_2: R29.2 U3.1 | length 250.8
  Top Layer w8: R29.2@2984.2,3718.48 v1(2984.2,3761.98) ; v1(3139.2,3761.98) 3166.64,3789.42 U3.1@3180.14,3789.42
  Bottom Layer w8: v1(2984.2,3761.98) v1(3139.2,3761.98)
NetR30_1: R30.1 R37.2 U3.7 | length 157.7
  Top Layer w9: U3.7@3278.57,3864.23 3301.44,3864.23
  Top Layer w20: 3301.44,3864.23 3324.2,3886.98 R37.2@3362.7,3886.98 3364.2,3885.49 R30.1@3364.2,3823.48
NetR31_2: R31.2 U3.12 | length 249.4
  Top Layer w8: v1(3119.2,3876.98) 3124.2,3876.98 3134.2,3866.98 3177.39,3866.98 U3.12@3180.14,3864.23 ; v1(3196.98,3996.5) 3196.98,4024.76 R31.2@3199.2,4026.98
  Bottom Layer w8: v1(3119.2,3876.98) 3196.98,3954.76 v1(3196.98,3996.5)
NetR36_2: R36.2 U3.8 | length 141.5
  Top Layer w8: U3.8@3258.89,3864.23 3258.89,3886.67 3279.2,3906.98 3305.7,3906.98 3330.7,3931.98 R36.2@3330.7,3960.49
NetR38_2: R38.2 U4.2 | length 133
  Top Layer w8: R38.2@2362.4,3530.5 2362.4,3569 2377.4,3584 2397.4,3584 2417.72,3604.32 U4.2@2417.72,3628.88
NetR39_1: R39.1 U4.8 | length 259.9
  Top Layer w9: U4.8@2437.4,3739.12 2437.4,3784
  Top Layer w20: 2437.4,3784 R39.1@2437.4,3999
NetR42_1: R42.1 U5.2 | length 62.2
  Top Layer w15: U5.2@2823.21,2589.99 2823.45,2590.23 R42.1@2885.31,2590.23
NetR42_2: R42.2 R43.2 R48.2 R49.1 R118.2 U6.5 | length 350.7
  Top Layer w15: R118.2@2950.31,2660 2948.3,2657.99 R42.2@2948.3,2590.23 2948.81,2589.73 R48.2@2948.81,2524.73 R49.1@3012.81,2524.73 ; R43.2@3013.94,2592.7 3012.81,2591.57 R49.1@3012.81,2524.73 ; U6.5@3094.52,2525.23 3094.02,2524.73 R49.1@3012.81,2524.73
NetR43_1: R43.1 TP4.1 | length 122.8
  Top Layer w15: R43.1@3013.94,2655.69 3013.94,2700.66 TP4.1@3069,2755.72
NetR44_1: R44.1 U6.1 U6.2 | length 209.2
  Top Layer w15: U6.2@3309.09,2425.23 3271.51,2425.23 3262,2415.72 3262,2385.72 3272.49,2375.23 U6.1@3309.09,2375.23 R44.1@3385.85,2375.22
NetR45_1: R45.1 U6.6 U6.7 | length 287.3
  Top Layer w15: U6.7@3094.52,2425.23 3065.49,2425.23 3055,2435.72 3055,2464.72 3065.51,2475.23 U6.6@3094.52,2475.23 3141.51,2475.23 3162.31,2496.04 R45.1@3162.31,2590.23
NetR47_2: R47.2 U6.3 | length 87.5
  Top Layer w15: U6.3@3309.09,2475.23 3393.81,2475.23 R47.2@3395.81,2473.24
NetR48_1: R48.1 U7.6 | length 72.5
  Top Layer w15: U7.6@2876.41,2461.44 2948.51,2461.44 R48.1@2948.81,2461.74
NetR50_1: R50.1 U9.2 | length 143.2
  Top Layer w15: R50.1@3400,3232.5 3542.5,3232.5 U9.2@3543,3233
NetR53_1: R53.1 U17.9 | length 507.9
  Top Layer w10: U17.9@820.96,888.64 861.2,888.64 v1(882.53,909.97)
  Top Layer w20: R53.1@891.27,1247.09 892.36,1246 v1(935,1246)
  Bottom Layer w15: v1(882.53,909.97) 862.22,930.28 862.22,1205.22 903,1246 v1(935,1246)
NetR54_1: R54.1 R56.2 R96.1 | length 128.7
  Top Layer w20: R54.1@449.29,828.66 449.66,828.29 R56.2@514.35,828.29 513.92,828.71 R96.1@513.92,891.61
NetR55_1: R55.1 U18.1 | length 96.5
  Top Layer w10: 2598.35,1735.89 U18.1@2598.35,1758.31
  Top Layer w15: 2598.35,1735.89 2598.24,1735.78 2598.24,1662.27 R55.1@2598.5,1662
NetR56_1: R56.1 R58.2 U17.3 | length 278.9
  Top Layer w10: R58.2@514.35,752.11 514.35,776.79 525.84,788.29 570.84,788.29 577.34,794.79 R56.1@577.34,828.29 613.84,828.29 654.51,868.96 U17.3@710.72,868.96
NetR57_2: R57.2 U18.4 | length 89.9
  Top Layer w10: U18.4@2675.12,1758.31 2691.54,1758.31 2721.16,1787.93 R57.2@2752.73,1787.93
NetR64_1: R64.1 R73.2 U20.18 | length 155.3
  Top Layer w10: R64.1@1630.93,1765.99 1663.87,1733.04 U20.18@1709.58,1733.04
  Top Layer w15: R64.1@1630.93,1765.99 R73.2@1630.93,1828.99
NetR65_1: R65.1 R69.2 U21.3 | length 143.9
  Top Layer w20: 2957.33,898.68 U21.3@3101.26,898.68
NetR67_1: R67.1 R74.2 TP13.1 U20.12 | length 295.3
  Top Layer w10: R74.2@1768.93,1895 1768.93,1844.63 1810.96,1802.6 U20.12@1810.96,1788.16
  Top Layer w15: R74.2@1768.93,1895 R74.2@1768.93,1902.99 1769.93,1901.99 R67.1@1834.94,1901.99 1834.94,1976.06 TP13.1@1819,1992
NetR68_1: R68.1 TP12.1 U20.16 | length 280.1
  Top Layer w10: TP12.1@1581.43,1977.99 1590,1977.99 1630.93,1937.06 R68.1@1630.93,1891.99 1667.12,1855.8 1667.12,1786.89 1681.6,1772.41 U20.16@1709.58,1772.41
NetR71_1: R71.1 U21.2 | length 181.4
  Top Layer w15: R71.1@2954.12,1031.31 3036.75,948.68 U21.2@3101.26,948.68
NetR72_1: R72.1 U20.10 | length 275.8
  Top Layer w10: U20.10@1853.28,1752.73 1879.95,1752.73 1889.12,1761.89 v6(1889.12,1778.89)
  Top Layer w20: R72.1@1965.12,1870.39 2005.62,1870.39 v2(2006.12,1870.89)
  Bottom Layer w15: v6(1889.12,1778.89) 1953.12,1778.89 2006.12,1831.89 v2(2006.12,1870.89)
NetR75_1: R75.1 U24.4 | length 83.5
  Top Layer w15: U24.4@1073.32,3407.79 1073.32,3382.06 R75.1@1114.18,3341.2
NetR79_1: R79.1 U26.6 | length 93.1
  Top Layer w15: R79.1@2359.18,671.64 2390.64,671.64 2417.05,698.05 U26.6@2441.33,698.05
NetR82_1: R82.1 R84.2 U27.4 | length 165.8
  Top Layer w20: R82.1@2066.54,1249.39 R84.2@2129.54,1249.39 2130.54,1248.39 U27.4@2130.54,1147.02
NetR86_2: R86.2 TP38.1 U30.2 | length 190.5
  Top Layer w15: R86.2@2424.25,2926.5 2428,2930.24 U30.2@2485.85,2930.24 2485.85,2963.85 2516.2,2994.2 TP38.1@2516.2,3045
NetR87_2: R87.2 TP9.1 U31.1 | length 206.4
  Top Layer w15: TP9.1@2795.06,2970.6 2795.06,3027.11 2821,3053.05 R87.2@2821,3092.7 2824.47,3096.18 2867.43,3096.18 U31.1@2885.6,3078
NetR88_1: R88.1 R89.2 R90.2 U32.7 | length 191
  Top Layer w15: R90.2@168,1874.5 R89.2@231.11,1874.5 232.11,1875.5 R88.1@295,1875.5 294.73,1875.24 U32.7@294.73,1812.08
NetR91_1: R91.1 R92.2 R93.2 U35.7 | length 191
  Top Layer w15: R93.2@792.09,1876.45 855.2,1876.45 856.2,1877.45 919.09,1877.45 918.82,1877.18 U35.7@918.82,1814.02
NetR95_1: R95.1 U23.2 U23.6 | length 255.6
  Top Layer w15: R95.1@3125,1402 3124.2,1402.8 U23.6@3124.2,1475.4 3124.2,1549.2 3149.8,1574.8 U23.2@3149.8,1646.66
NetR96_2: R96.2 TP28.1 U17.2 | length 459
  Top Layer w10: v2(633.36,888.64) U17.2@710.72,888.64
  Top Layer w15: R96.2@579.88,888.64 v2(633.36,888.64)
  Bottom Layer w15: TP28.1@385,696 408,696 600.64,888.64 v2(633.36,888.64)
NetR97_1: R97.1 U32.5 U42.1 | length 1520.3
  Top Layer w10: U32.5@318.35,1692 318.35,1683.65 334,1668 392.5,1668 R97.1@404.5,1680 441.5,1643 562,1643 624,1705 624,2033 675.87,2084.87 1237.13,2084.87 1276,2046 1276,1971 1296.31,1950.69 U42.1@1328.87,1950.69
NetR99_1: R99.1 U42.6 | length 104.8
  Top Layer w10: U42.6@1387.13,1950.69 1427.18,1950.69 R99.1@1473,1996.5
NetR100_1: R100.1 U42.4 | length 87.4
  Top Layer w10: U42.4@1387.13,1911.32 1472.82,1911.32 R100.1@1474,1912.5
NetR103_1: R103.1 TP33.1 U43.3 | length 182
  Top Layer w20: TP33.1@681.81,3421.25 682.31,3421.75 R103.1@682.31,3535.25 682.67,3535.61 U43.3@682.67,3602.85
NetR104_1: R104.1 U43.5 | length 80.4
  Top Layer w20: U43.5@790.94,3640.25 815.81,3640.25 841.3,3614.75 R104.1@860.81,3614.75
NetR110_2: R110.2 U18.2 | length 188.7
  Top Layer w10: U18.2@2623.94,1758.31 2623.94,1729.06 2653,1700 2712.47,1700 R110.2@2754.09,1658.39
NetR111_2: R111.2 U18.3 | length 127.5
  Top Layer w10: U18.3@2649.53,1758.31 2649.53,1744.47 2673,1721 R111.2@2753.5,1721
NetR117_1: R117.1 U50.3 | length 88
  Top Layer w15: R117.1@3331.25,2980.39 3360.59,2980.39 3380.61,3000.41 U50.3@3410.93,3000.41
NetR118_1: R118.1 U51.5 U51.6 | length 106.6
  Top Layer w15: U51.5@2913,2792.17 U51.6@2950.4,2792.17 2950.31,2792.08 R118.1@2950.31,2722.99
NetR119_2: R119.2 TP46.1 U52.1 | length 175.3
  Top Layer w15: TP46.1@2572.96,3225 2608.06,3189.89 R119.2@2608.06,3128.81 2614.58,3135.32 U52.1@2669.95,3135.32
NetS1_2: S1.2 TP30.1 U17.4 | length 535.1
  Top Layer w10: v2(635.84,808.29) 676.83,849.27 U17.4@710.72,849.27
  Top Layer w15: S1.2@574.59,644.65 v2(574.59,692.96)
  Bottom Layer w15: TP30.1@385,537 540.96,692.96 v2(574.59,692.96) 574.59,747.04 v2(635.84,808.29)
NetTP48_1: TP48.1 U52.4 | length 218.9
  Top Layer w15: U52.4@2744.76,3243.59 2782.09,3243.59 TP48.1@2910.5,3372
NetU11_1: U11.1 U11.2 U11.3 U11.7@534.88,2579.43 U12.1 U12.2 U12.3 U12.7@535.17,2458.16
  other v3: 513.51,2458.16 556.82,2458.16 513.23,2579.43 556.54,2579.43
NetU14_1: U14.1 U14.2 U14.3 U14.7@382.24,3593.61 U15.1 U15.2 U15.3 U15.7@381.99,3473.08
  other v3: 360.33,3473.08 403.64,3473.08 360.59,3593.61 403.89,3593.61
NetU16_1: U16.1 U16.2 U16.3 U16.7@374.8,1213 U19.1 U19.2 U19.3 U19.7@374.55,1087.82 | length 86.6
  Bottom Layer w15: v3(352.89,1087.82) v3(396.2,1087.82) ; v3(353.14,1213) v3(396.45,1213)
NetU22_1: U22.1 U22.2 U22.3 U22.7@3245.59,1873.61 U41.1 U41.2 U41.3 U41.7@3244.59,1749.61 | length 86.6
  Bottom Layer w15: v3(3222.94,1749.61) v3(3266.24,1749.61) ; v3(3223.94,1873.61) v3(3267.24,1873.61)
NetU46_1: U46.1 U46.2 U46.3 U46.7@374.65,268 U47.1 U47.2 U47.3 U47.7@374.41,142.82 | length 86.6
  Bottom Layer w15: v3(352.75,142.82) v3(396.06,142.82) ; v3(353,268) v3(396.31,268)
NetU48_1: U48.1 U48.2 U48.3 U48.7@1168.26,4068.71 U49.1 U49.2 U49.3 U49.7@1168.57,4188.33
  other v3: 1146.61,4068.71 1189.92,4068.71 1146.92,4188.33 1190.22,4188.33
OUT: J3.4 J21.2 | length 578.9
  Bottom Layer w70: J3.4@1310.98,4168.71 1310.98,4230.71 1340.98,4260.71 1707.98,4260.71 J21.2@1783.98,4184.71
PG_N: Q3.1 R6.1 R98.2 U35.5 | length 415.5
  Top Layer w10: U35.5@942.44,1693.94 942.44,1686.25 960.75,1667.94 1010.55,1667.94 R98.2@1070,1608.5 1071,1607.5 R6.1@1133.72,1607.5 1258.5,1607.5 1276.4,1625.4 Q3.1@1276.4,1659.24
REF_2.5V: C50.1 R44.2 TP5.1 | length 218.5
  Top Layer w15: TP5.1@3267.85,2261.72 3318.35,2312.23 R44.2@3385.85,2312.23 3463.35,2312.23 C50.1@3464.85,2313.72
REF_2.5V_A: C52.1 R45.2 TP6.1 | length 215.3
  Top Layer w15: TP6.1@3217.85,2792.72 3225.3,2785.27 C52.1@3225.3,2668.72 ; R45.2@3225.3,2590.23 C52.1@3225.3,2668.72 ; C52.1@3234.81,2668.23 3225.79,2668.23 C52.1@3225.3,2668.72
SEN+: C63.1 R55.2 R77.1 R78.1 TP8.1 U18.7 U26.4 | length 1905.5
  Top Layer w10: C63.1@2600,1956.5 2600,1915.01 2623.94,1891.07 U18.7@2623.94,1868.54
  Top Layer w15: U26.4@2441.33,749.23 2424.87,765.68 2424.87,878.53 2663,1116.65 R78.1@2663,1473.24 ; v6(2572,1896) 2572,1928.5 C63.1@2600,1956.5 ; R55.2@2661.5,1662 2661.82,1661.68 R77.1@2661.82,1579.43 R78.1@2661.82,1474.43 TP8.1@2771.43,1474.43
  Bottom Layer w15: v6(2572,1896) 2515,1896 2485,1866 2485,1764 TP8.1@2773,1476
SEN-: R76.2 U26.5 | length 810.9
  Top Layer w15: U26.5@2441.33,723.64 2414.36,723.64 2402,736 2402,888 2640.13,1126.13 2640.13,1361.53 R76.2@2610.23,1391.43
SENSE: C91.1 R79.2 R81.2 TP14.1 U29.4 | length 458.1
  Top Layer w10: 2195,687 2230.37,651.63 U29.4@2230.37,615.26
  Top Layer w15: 2195,687 2165,717 TP14.1@2165,773 2260.83,773 C91.1@2296.68,737.14 ; R79.2@2296.19,671.64 2296.19,736.65 C91.1@2296.68,737.14 ; R81.2@2357.68,737.14 C91.1@2296.68,737.14
TEMP_OUT: C57.2 R50.2 TP7.1 | length 187.2
  Top Layer w15: TP7.1@3213,3296 3213.5,3295.5 C57.2@3337,3295.5 R50.2@3400,3295.5
TEMP_OUT1: C136.2 R117.2 TP45.1 | length 277.4
  Top Layer w15: TP45.1@3095.39,2885 3172.87,2885 R117.2@3268.26,2980.39 C136.2@3268.26,3045.39
VCAPH: C118.1 U23.7 | length 152.5
  Top Layer w15: U23.7@3149.8,1479.34 3149.8,1518.8 3164,1533 C118.1@3257,1533
VCAPL: C118.2 U23.1 | length 125.4
  Top Layer w15: U23.1@3175.39,1646.66 3175.39,1612.61 3187,1601 3245,1601 C118.2@3257,1613
VDC_5V: C85.2 C87.2 C89.2 C90.2 C92.2 C94.2 C97.2 D12.1 R76.1 R77.2 R78.2 R80.2 R85.2 TP17.1 U25.2 U25.3 U25.4 U26.3 U27.1 U27.5 U29.2 | length 744.5
  Top Layer w10: C97.2@2209.68,493.64 2210.68,494.64 U29.2@2210.68,568.02
  Top Layer w15: U26.3@2522.04,749.23 2530.23,749.23 2557.68,776.68 C89.2@2557.68,821.64
  Top Layer w20: v2(1825.68,641.5) R85.2@1889,641.5 ; C97.2@2209.68,493.64 v2(2258.64,493.64) C90.2@2308.68,493.64 ; R80.2@2328.19,569.64 2329,570.45 v2(2329,615) ; C89.2@2557.68,821.64 v2@2557.68,879.6
  Top Layer w25: v2(2040,1148) 2040.98,1147.02 U27.5@2080.54,1147.02
  Bottom Layer w25: v2(2040,1148) 2042,1146 v2(2310,1146)
  other v2: 1822,833 2557.32,880.96 1822,891 1822,949 2496,1115 2496,1173 2481,1382 2481,1498
VDC_5V_1: C71.1 C72.1 C76.1 C83.2 C98.1 C119.1 L7.2 R67.2 R68.2 R97.2 R101.2 R102.2 TP11.1 U18.8 U20.9 U42.5 | length 3394.7
  Top Layer w10: C119.1@1377.62,2001 1358.93,1982.31 1358.93,1942.07 1370,1931 1359,1920 1359,1883 1388,1854 R102.2@1391.5,1854 ; U20.9@1853.28,1733.04 1907.28,1733.04 1918.12,1743.89 ; C98.1@2541.15,1868.54 U18.8@2598.35,1868.54
  Top Layer w20: R97.2@467.5,1680 553,1680 594,1721 v2(594,2038) ; C119.1@1377.62,2001 v2(1420,2001) ; v2(1525.21,1891.99) R68.2@1567.94,1891.99 ; R67.2@1897.93,1901.99 v2(1897.93,1944.08) ; 1918.12,1743.89 C83.2@1944.13,1769.89 1944.13,1779.12 1982.9,1817.89 2023.12,1817.89
  Top Layer w30: v2(1401.08,1499.92) R101.2@1401.08,1552.92
  Bottom Layer w30: v2(594,2038) 630,2074 1347,2074 v2(1420,2001) 1420,1893.99 ; v2(1401.08,1499.92) 1365,1536 1365,1838.99 1420,1893.99 ; TP11.1@2232.12,1998.89 2153.23,1920 1922.01,1920 v2(1897.93,1944.08) 1821.83,1867.99 1549.21,1867.99 v2(1525.21,1891.99) 1422,1891.99 1420,1893.99
VDC_5V_2: C64.1 C73.1 C80.1 C81.1 C134.1 R66.2 TP40.1 U18.6 U21.7 | length 441.6
  Top Layer w12: U18.6@2649.53,1868.54 2649.53,1937.02 C64.1@2664.5,1952
  Top Layer w20: C64.1@2664.5,1952 2664.5,1987.5 v2(2680,2003) v2(2713,2036) ; C73.1@2875.86,583.68 R66.2@2875.86,672.68
  Bottom Layer w50: v2(3218,639) 3275,639 TP40.1@3347,567
  other v2: 3124,639 3171,639 2841.86,671
VIN: J3.2 J20.2 U48.4 U48.5 U48.6 | length 120.2
  Top Layer w20: 1104.3,4030.33 U48.4@1142.67,4030.33 U48.5@1168.26,4030.33 U48.6@1193.85,4030.33 1224.53,4030.33
VIN1: C65.1 J7.1 J11.1 J17.1 U16.4 U16.5 U16.6 | length 67.9
  Top Layer w10: U16.6@349.2,1251.39 U16.5@374.8,1251.39 U16.4@400.39,1251.39 417.09,1251.39
VOUT1: C66.1 J9.1 J10.1 J16.2 U17.10 U40.4 U40.5 U40.6 | length 282.2
  Top Layer w10: 815.88,913.25 815.88,908.33 U17.10@820.96,908.33
  Top Layer w15: 815.88,913.25 815.88,1038.33 835.84,1058.29 ; 971.71,1066.61 U40.4@990.41,1066.61 U40.5@1016,1066.61 U40.6@1041.59,1066.61 1064.61,1066.61 1083,1085
WDI: TP10.1 U31.4 | length 162.4
  Top Layer w15: U31.4@2960.4,3178.4 2960.4,3179.03 3068.54,3287.18 TP10.1@3068.54,3296
pads on no net: FID1.1 FID2.1 FID3.1 H1.0 H2.0 H3.0 H4.0 H5.0 H6.0 H7.0 H8.0 H9.0 H10.0 Q1.9@3105.08,1180.91 Q1.9@3105.08,1238 Q1.9@3105.08,1295.09 Q1.9@3141.69,1238 Q1.9@3175.16,1180.91 Q1.9@3175.16,1238 Q1.9@3175.16,1295.09 S1.MH1 S1.MH2 S1.MP1 S1.MP2 S1.MP3 S1.MP4 U2.7 U2.12 U2.20 U3.13@3202.43,3826.82 U3.13@3256.29,3826.82 U7.1 U7.3 U7.7 U7.8 U8.3 U10.4 U10.5 U11.7@517.17,2579.43 U11.7@552.6,2579.43 U12.7@517.45,2458.16 U12.7@552.88,2458.16 U14.7@364.52,3593.61 U14.7@399.96,3593.61 U15.7@364.27,3473.08 U15.7@399.7,3473.08 U16.7@357.08,1213 U16.7@392.51,1213 U17.11@756,808.72 U17.11@756,929.19 U17.11@765.84,844.16 U17.11@765.84,893.76 U17.11@775.68,808.72 U17.11@775.68,929.19 U19.7@356.83,1087.82 U19.7@392.26,1087.82 U20.7 U20.19 U20.23 U20.27 U20.28 U20.29 U20.30 U20.31@1761.75,1606.66 U20.31@1761.75,1651.54 U20.31@1761.75,1696.43 U20.31@1761.75,1741.31 U20.31@1801.12,1606.66 U20.31@1801.12,1651.54 U20.31@1801.12,1696.43 U20.31@1801.12,1741.31 U22.7@3227.87,1873.61 U22.7@3263.31,1873.61 U23.3 U23.5 U24.1 U24.3 U25.8 U28.3 U32.8 U32.9 U32.10 U32.11@230.56,1745.15 U32.11@271.11,1745.15 U32.11@311.66,1745.15 U34.7@364.57,1993 U34.7@400,1993 U35.8 U35.9 U35.10 U35.11@854.65,1747.09 U35.11@895.2,1747.09 U35.11@935.75,1747.09 U36.7@988.66,1996.6 U36.7@1024.09,1996.6 U38.7@2309,4088.94 U38.7@2309,4124.37 U39.7@2554,4089 U39.7@2554,4124.43 U40.7@998.28,1105 U40.7@1033.72,1105 U41.7@3226.87,1749.61 U41.7@3262.31,1749.61 U45.4 U46.7@356.94,268 U46.7@392.37,268 U47.7@356.69,142.82 U47.7@392.12,142.82 U48.7@1150.55,4068.71 U48.7@1185.98,4068.71 U49.7@1150.85,4188.33 U49.7@1186.29,4188.33 U50.1 U50.5

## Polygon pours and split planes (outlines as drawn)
AGND on Bottom Layer "net" (solid, remove dead copper, pour order 586): 18 vertices, not listed, extent 32.35,2189.72 3604,4303
GND on Bottom Layer "net" (solid, remove dead copper, pour order 584): 1187,2190.72 2289.94,2190.72 2315,2215.78 2315,3182 2280,3217 1500.92,3217 1458.92,3259 1458.92,3855.13 1416.05,3898 95.59,3898 31.51,3842 31.51,2210.21 51,2190.72
GND1 on Bottom Layer "Top Layer-No Net" (solid, remove dead copper, pour order 524): 834,2091 3555,2091 3591,2055 3591,446 3559,414 94,414 45,463 26,482 26,2061 53,2088 56,2091
DCDC_-10P5V on Bottom Layer "vd" (solid, remove dead copper, pour order 520): 36 vertices, not listed, extent 662.09,1668.86 1161.09,2064.48
+24V_IN1 on Bottom Layer "vd" (solid, remove dead copper, pour order 512): 24 vertices, not listed, extent 266,1279 1156,1710
DCDC_+10P5V on Bottom Layer "Top Layer-No Net" (solid, pour order 264): 344,1837 404,1837 537,1837 542,1842 544,1844 544,1852 544,1941 534,1951 343,1951 335,1943 335,1912 335,1846
+24V_IN on Bottom Layer "net" (solid, remove dead copper, pour order 462): 1459,1690 1459,1419 1416,1376 1211,1376 1192,1357 1192,1291 1202.14,1281.14 1510.86,1281.14 1511,1281 1551.5,1321.5 1551.5,1630.5 1590.12,1669.12 1590.12,1786.89 1586.12,1790.89 1559.89,1790.89
VDC_5V on Bottom Layer "net" (solid, remove dead copper, pour order 434): 18 vertices, not listed, extent 1731,430 2702,1659
VDC_5V_2 on Bottom Layer "net" (solid, remove dead copper, pour order 432): 21 vertices, not listed, extent 2662,565.89 3272.12,2090
NetC67_2 on Bottom Layer "g" (solid, remove dead copper, pour order 312): 39 vertices, not listed, extent 550.84,463.29 1545.84,1056.66
GND1 on Bottom Layer "Top Layer-No Net" (solid, pour order 266): 23 vertices, not listed, extent 1584,811 1706,1331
